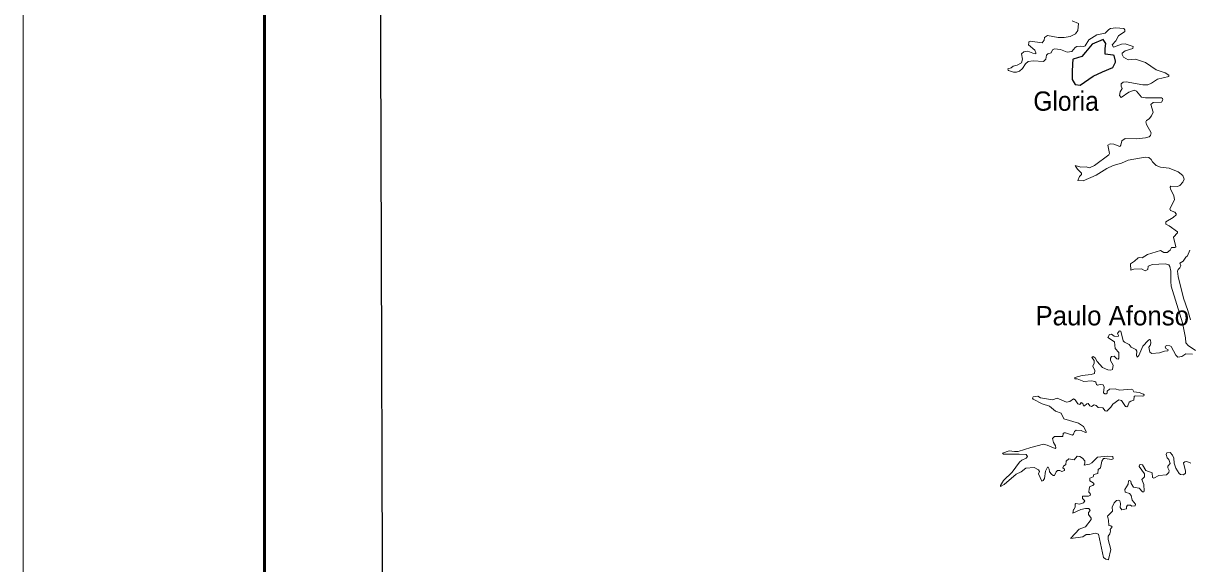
# Model space of a CAD drawing. Extents: x 553962 to 842807, y 8883888 to 9032388.
# Drawn here: x 553962 to 584142, y 8954118 to 8968117 of the extents above; entities that cross this region are included whole.
import ezdxf
from ezdxf.enums import TextEntityAlignment as Align

# ---------------------------------------------------------------- set-up
doc = ezdxf.new("R2010")
doc.units = 0
doc.header["$LTSCALE"] = 160
for name, color, linetype, lineweight in [('1', 7, 'Continuous', 13), ('21', 7, 'Continuous', 25), ('28', 7, 'Continuous', 13)]:
    doc.layers.add(name, color=color, linetype=linetype, lineweight=lineweight)
doc.layers.add('29', color=7, linetype='Continuous')

msp = doc.modelspace()

# ---------------------------------------------------------------- linework, layer by layer
at = {"layer": '1'}
msp.add_lwpolyline([(842807.3, 9032387.8), (842807.3, 8883887.8), (553961.7, 8883887.8), (553961.7, 9032387.8)], close=True, dxfattribs=at)
at = {"layer": '1', "lineweight": 53}
msp.add_lwpolyline([(840307.3, 9029887.8), (840307.3, 8886387.8), (560211.7, 8886387.8), (560211.7, 9029887.8)], close=True, dxfattribs=at)
at = {"layer": '1', "lineweight": 25}
msp.add_lwpolyline([(563033.9, 9026438.8), (793061.1, 9026438.8), (793495.6, 8889836.8), (563468.3, 8889836.8)], close=True, dxfattribs=at)
at = {"layer": '21', "lineweight": 13}
for points in [[(581126.5, 8968182.3), (581290, 8968109.6), (581273.1, 8967931.4), (581209.4, 8967844.3), (581071.3, 8967774.2), (580918.4, 8967748.8), (580765.4, 8967750.9), (580485.3, 8967797.5), (580404.5, 8967748.8), (580399.9, 8967680.5), (580349.3, 8967615), (580036, 8967653.3), (580002.2, 8967641.4), (579997.9, 8967607)], [(579471.8, 8966890.6), (579601.1, 8966852.3), (579686.3, 8966854.5), (579762.8, 8966875.7), (579835, 8966943.6), (579915.9, 8967069.1), (579983.5, 8967124), (580111.4, 8967147.6), (580385.3, 8967130.7), (580438.2, 8967185.8), (580457.7, 8967294.3), (580493.6, 8967323.8), (580582.4, 8967349.3), (580614.4, 8967431.8), (580667.5, 8967459.7), (580825.2, 8967438.5), (580998.9, 8967368.6), (581119.9, 8967389.7), (581198.8, 8967489.5), (581241.1, 8967517), (581332, 8967527.8), (581427.3, 8967517.2), (581459.8, 8967529.9), (581553.6, 8967684.9), (581763.8, 8967818.8), (581982.3, 8967861.3), (582071.9, 8967959), (582116.5, 8967984.5), (582256.4, 8967999.4), (582458.3, 8967980.2), (582488.1, 8967944.1), (582488.1, 8967904.1), (582326.8, 8967791.2), (582254.4, 8967663.6), (582159.1, 8967561.8), (582195.1, 8967498.2), (582401.1, 8967574.5), (582494.3, 8967589.4), (582706.9, 8967517.1), (582694, 8967461.9), (582494.8, 8967400.4), (582416.1, 8967347.1), (582416, 8967311.4), (582456.7, 8967236.5), (582571.1, 8967166.8), (582760.3, 8967185.7), (583025.6, 8967098.7), (583297.3, 8966909.8), (583531.2, 8966831), (583624.6, 8966771.3), (583624.5, 8966739.8), (583331.5, 8966667.5), (583178.8, 8966563.5), (583085.1, 8966527.3), (582953.4, 8966525.2), (582524.1, 8966597.4), (582441.5, 8966588.8), (582396.9, 8966552.7), (582390.2, 8966492.9), (582415.8, 8966429.6), (582364.9, 8966338), (582346, 8966247.1), (582396.7, 8966191.8), (582588.1, 8966331.8), (582728.2, 8966384.9), (582789.8, 8966359.4), (582915.7, 8966200), (583025.6, 8966183.2), (583439.6, 8966189.4), (583465.2, 8966170.4), (583475.9, 8966134.3), (583441.9, 8966077), (583223.5, 8966068.5), (583165.9, 8966013.2), (583225.2, 8965811.2), (583178, 8965717.2), (583114.8, 8965645.7), (583049.1, 8965601.1), (583034.2, 8965562.9), (583051.2, 8965492.5), (583170, 8965280.6), (583148.8, 8965212.4), (583119.2, 8965176.5), (583025.6, 8965146.5), (582792, 8965127.4), (582498.3, 8965133.6), (582407.6, 8965076.4), (582384.1, 8964957.7), (582356.2, 8964921.4), (582201.2, 8964983), (582107.7, 8964995.5), (582107.7, 8964995.5), (582044.3, 8964959.3), (582095.1, 8964745.1), (582073.9, 8964708.9), (581702.2, 8964430.7), (581572.4, 8964375.4), (581483.4, 8964396.6), (581351.7, 8964392.4), (581198.1, 8964430.9), (581209.9, 8964412.9)], [(579997.9, 8967607), (579992.3, 8967561.8), (580161, 8967421.7), (580187.4, 8967349.7), (580181.1, 8967330.4), (580105, 8967343), (580105, 8967343), (579979.2, 8967396.1), (579873.1, 8967378.9), (579813.9, 8967330.2), (579835, 8967188.5), (579811.7, 8967092.6), (579704, 8967033.2), (579595, 8967007.3), (579541.6, 8966967.5), (579455.3, 8966936.2), (579467.6, 8966902.2), (579471.8, 8966890.6)], [(581209.9, 8964412.9), (581258.4, 8964339.1), (581362.3, 8964235), (581362.2, 8964201), (581311.5, 8964150.2), (581271.6, 8964044.5), (581411.2, 8964039.8), (581742.6, 8964184.2), (582018.8, 8964356.3), (582184.7, 8964432.8), (582405.6, 8964492.4), (582571.3, 8964568.8), (583013.2, 8964651.5)], [(583013.2, 8964651.5), (583110.6, 8964638.7), (583174.1, 8964592.2), (583202.2, 8964526), (583302.1, 8964434.8), (583412.2, 8964392.4), (583632.9, 8964364.8), (583871.3, 8964269), (583992.3, 8964171.2), (584023.8, 8964077.5), (583992, 8964005.7), (583909.5, 8963912.6), (583854.1, 8963889), (583680, 8963897.4), (583661, 8963870), (583667.3, 8963822.9), (583756.3, 8963657.4), (583773.3, 8963547.2), (583654.7, 8963312.4), (583667.3, 8963264.5), (583784.2, 8963226), (583820, 8963181), (583815.2, 8963159.7), (583737.5, 8963086.2), (583548.2, 8962977.4), (583552.7, 8962911.8), (583639.8, 8962873.4), (583854, 8962716.3), (583853.2, 8962685.6), (583752.2, 8962580.2), (583807.2, 8962323.5), (583781.6, 8962306.4), (583692.8, 8962310.5), (583662.8, 8962238.5), (583584.3, 8962176.9), (583497.2, 8962176.9), (583410.3, 8962234), (583076.4, 8962125.7), (582940.9, 8962038.9), (582866.3, 8962051.4), (582832.4, 8962038.7), (582741.2, 8961953.9), (582632.6, 8961889.8), (582642.1, 8961718.4), (582724.2, 8961752), (582923.6, 8961760.4), (583013.1, 8961707.5), (583082.9, 8961741.4), (583093.8, 8961826.3), (583208.6, 8961873.1), (583535.2, 8961883.6), (583631.9, 8961861.4), (583656.7, 8961812.9), (583679.9, 8961694.8), (583675.7, 8961427), (583690.5, 8961308.2), (583979.3, 8960356.6), (584055.9, 8959969.5), (584064.3, 8959836.4), (584126, 8959774.3), (584315, 8959638.2)], [(584187.7, 8960432.6), (584121.2, 8960674.7), (584009.2, 8960993.4), (583869, 8961554.4), (583856.2, 8961694.6), (583866.6, 8961740.8), (583913.5, 8961781.7), (583936.8, 8961830.6), (583913.8, 8961907.2), (584002.7, 8961956), (584066.4, 8962055.5), (584113.2, 8962091.9), (584172.1, 8962236.3)], [(582299.4, 8960082.5), (582322.5, 8960029), (582315.9, 8960001.7), (582208.1, 8960016.5), (582141.7, 8960063.2), (582091.2, 8960052.6), (582050.7, 8959980.4), (582220.4, 8959865.6), (582237.6, 8959695.7), (582330.8, 8959589.7), (582331, 8959439.1), (582316.1, 8959415.5), (582278, 8959423.9), (582214.1, 8959495.9), (582142.1, 8959487.4), (582116.5, 8959440.5), (582118.7, 8959385.4), (582188.6, 8959260.2), (582167.3, 8959147.5), (582129.4, 8959128.6), (582046.5, 8959141.3), (581908.3, 8959202.9), (581774.6, 8959353.5), (581717.2, 8959451.2), (581670.4, 8959485.2), (581634.5, 8959460), (581691.6, 8959378.9), (581692.1, 8959315.5), (581659.8, 8959239), (581708.6, 8959122.1), (581699.9, 8959047.7), (581615.1, 8959015.9), (581381.2, 8958994.6), (581190.6, 8958937.3), (581194.6, 8958907.9), (581251.8, 8958907.5), (581424.2, 8958839.7), (581627.9, 8958854.5), (581712.6, 8958841.7), (581738.2, 8958822.6), (581757.5, 8958761.1), (581780.6, 8958746.3), (581848.8, 8958761), (581922.9, 8958748.3), (581955, 8958692.5), (581933.7, 8958544.9), (581967.3, 8958516.9), (582005.7, 8958514.7), (582027, 8958531.6), (582031.7, 8958591.2), (582095.5, 8958639.9), (582235.7, 8958646.3), (582353.6, 8958614.5), (582656.2, 8958635.6), (582696.2, 8958625.2), (582719.7, 8958570.1), (582859.9, 8958554.9), (582974.4, 8958510.4), (582989.4, 8958491.2), (582983.1, 8958470.1), (582953.2, 8958455.2), (582755.7, 8958467.7), (582732.5, 8958448.5), (582721.7, 8958357.6), (582641.2, 8958331.9), (582596.6, 8958300), (582568.8, 8958204.3), (582543.4, 8958185.4), (582505.1, 8958189.8), (582401, 8958344.6), (582332.9, 8958361.5), (582178.1, 8958253.3), (582127.2, 8958170.8), (582019.4, 8958072.8), (581978.5, 8958081.4), (581920, 8958154), (581799.4, 8958164.3), (581748.9, 8958212.8), (581696, 8958236.1), (581627.9, 8958191.9), (581578.9, 8958209), (581539.6, 8958263.8), (581539.6, 8958263.8), (581504.7, 8958259.6), (581447.3, 8958208.8), (581420.4, 8958210.8), (581400.5, 8958268.1), (581360.2, 8958291.4), (581319.8, 8958245), (581270.9, 8958257.8), (581203.2, 8958359.3), (581156.5, 8958384.9), (581064.7, 8958323.4), (580973.9, 8958304.4), (580740.2, 8958401.9), (580612.5, 8958359.6), (580303, 8958410.4), (580235.9, 8958453.9), (580113.2, 8958444.3), (580098.5, 8958410.3), (580099.6, 8958407.9)], [(584244.7, 8959542.8), (584070.6, 8959557.6), (583962.4, 8959487.6), (583862.6, 8959466.3), (583809.5, 8959521.5), (583684, 8959740.2), (583651.7, 8959765.9), (583580.3, 8959774.3), (583541.6, 8959757), (583531.3, 8959731.8), (583550.2, 8959691.6), (583607.5, 8959661.8), (583603.4, 8959628), (583514.4, 8959627.7), (583382, 8959578.8), (583184.5, 8959559.9), (583138.3, 8959595.9), (583108.6, 8959723.3), (583108.6, 8959723.3), (583144.6, 8959774.5), (583159.4, 8959833.8), (583148.8, 8959914.2), (583125.3, 8959922.9), (583089.5, 8959901.9), (582957.8, 8959753.2), (582851.4, 8959515.1), (582809, 8959470.7), (582792, 8959510.9), (582795.6, 8959619.4), (582771.8, 8959670.2), (582656.1, 8959725.5), (582596.3, 8959797.7), (582477.6, 8959853), (582443.6, 8959893.3), (582381.9, 8960139.6), (582362.8, 8960152.2), (582339.6, 8960143.8), (582299.4, 8960082.5)], [(580099.6, 8958407.9), (580111.4, 8958382.8), (580349.1, 8958255.5), (580540.2, 8958198), (580692.5, 8958073.2), (580835.5, 8958013.2), (580910.1, 8957870.9), (581289.9, 8957760.6), (581421.8, 8957673.3), (581496, 8957526.9), (581466.2, 8957520.6), (581357.9, 8957571.4), (581224.5, 8957577.8), (581188.5, 8957544.2), (581162.8, 8957476.1), (581130.8, 8957450.5), (580955.2, 8957509.6), (580919.1, 8957507.7), (580890.9, 8957486.6), (580886.3, 8957410), (580667.8, 8957416.2), (580619.2, 8957363.6), (580640, 8957259.4), (580693.2, 8957169.7), (580701.6, 8957122.8), (580682.8, 8957104.2), (580477.4, 8957190.9), (580383.3, 8957210.3), (580056.8, 8957131.9), (579729, 8957025.6), (579635.1, 8957021.3), (579494.9, 8957040.3), (579320.1, 8956982.2), (579330.4, 8956970.9)], [(579330.4, 8956970.9), (579346.5, 8956953.4), (579750.3, 8956955.4), (579931, 8956942.9), (579964.5, 8956895.9), (579936.8, 8956853.3), (579818, 8956796.1), (579763, 8956751.6), (579569.6, 8956488.2), (579346.5, 8956275.5), (579267.5, 8956147.6), (579269.2, 8956128.5)], [(582066.7, 8954223.6), (582129.2, 8954489.4), (582057, 8954744.1), (582052.8, 8954828.8), (582103.7, 8954893.1), (582120.6, 8954960.7), (582108.2, 8955005.5), (582163, 8955071.2), (582129.2, 8955100.8), (582072.2, 8955107.3), (582061.2, 8955249.4), (582040.1, 8955351.6), (582171.5, 8955478.9), (582157.1, 8955581.8), (582214, 8955691.2), (582269.6, 8955750.9), (582321.7, 8955763.6), (582358.6, 8955744.6), (582379.8, 8955678.5), (582367.2, 8955576.8), (582411.8, 8955511), (582534.7, 8955540.7), (582532.9, 8955594), (582558.3, 8955632), (582632.4, 8955638.4), (582671.6, 8955604.4), (582751.6, 8955613.2), (582766.3, 8955661.9), (582675.3, 8955763.5), (582649.7, 8955884.6), (582613.2, 8955937.9), (582498.8, 8955974.4), (582492.5, 8956044.1), (582570.9, 8956175.6), (582579.8, 8956265), (582607.4, 8956273.4), (582645.2, 8956252.4), (582652.2, 8956196.2), (582711.3, 8956099.4), (582856.3, 8956071.3), (582947.1, 8955976.2), (582976.7, 8955976.2), (582991.4, 8955993), (582978.9, 8956171.6), (582932.2, 8956297.6), (582995.8, 8956371.3), (583000.1, 8956445.4), (583000.1, 8956445.4), (582857.8, 8956639.1), (582866.4, 8956681.3), (582889.9, 8956689.8), (582944.7, 8956675), (583036.3, 8956532.7), (583197.6, 8956473.1), (583204.2, 8956354.3), (583235.8, 8956333.2), (583365.5, 8956403), (583569.2, 8956422.2), (583628.9, 8956482), (583635.2, 8956528.2), (583599.3, 8956600.4), (583603.4, 8956642.9), (583660.7, 8956715.7), (583628.7, 8956817.4), (583586.5, 8956859.9), (583561.1, 8956946.9), (583580.2, 8956987.2), (583660.8, 8957002.1), (583724.4, 8956925.6), (583756.3, 8956851.3), (583767, 8956723.9), (583805.3, 8956596.4), (583896.6, 8956454.1), (583928.7, 8956432.8), (584011.2, 8956420.2), (584055.8, 8956462.4), (584062.2, 8956515.4), (584011.4, 8956727.3), (584038.7, 8956757.6), (584094.1, 8956768.4), (584197.5, 8956726)], [(579269.2, 8956128.5), (579269.9, 8956121.1), (579359.2, 8956171.6), (579677.6, 8956436.9), (579805, 8956498.6), (579924, 8956592), (580136.6, 8956613.3), (580253.4, 8956549.5), (580274.6, 8956509.1), (580251.5, 8956443.2), (580340.8, 8956252.5), (580372.3, 8956271.5), (580408.5, 8956324.5), (580431.9, 8956511.2), (580482.8, 8956619.5), (580499.8, 8956617.5), (580531.6, 8956562.6), (580540.2, 8956494.7), (580586.8, 8956433.1), (580631.7, 8956403.2), (580663.4, 8956403.2), (580708.6, 8956501.7), (580744, 8956530.4), (580801.5, 8956530.5), (580856.8, 8956505.1), (580922.4, 8956530.5), (580922.5, 8956566.6), (580882.6, 8956601.5), (580901.5, 8956645.2), (580958.6, 8956687.6), (580969.4, 8956772.7), (581041.6, 8956834.2), (581175.2, 8956811), (581251.9, 8956904.3), (581326.2, 8956893.7), (581388, 8956855.3), (581453.6, 8956783.3), (581455.8, 8956719.8), (581434.7, 8956673.2), (581572.6, 8956696.3), (581630, 8956728.1), (581783.2, 8956880.5), (581783.2, 8956880.5), (582043.8, 8956902.2), (582180, 8956896), (582182.3, 8956832.5), (582150.4, 8956819.5), (581969.4, 8956847.3), (581933.5, 8956840.4), (581891.2, 8956774.6), (581857.1, 8956604.5), (581795.2, 8956554.8), (581787.1, 8956452), (581685.3, 8956432.7), (581666, 8956369.2), (581578.8, 8956332.5), (581581.2, 8956260.8), (581665.8, 8956214.1), (581693.6, 8956177.9), (581661.8, 8956146.1), (581585.5, 8956114.1), (581562.1, 8956061.3), (581560, 8955969.8), (581593.8, 8955933.6), (581597.9, 8955895.3), (581551.4, 8955867.9), (581390.2, 8955865.7), (581390.1, 8955804.1), (581449.3, 8955742.7), (581421.9, 8955695.9), (581310.1, 8955657.7), (581215.8, 8955674.4), (581201, 8955657.4), (581200.8, 8955593.5), (581179.9, 8955534.8), (581160.6, 8955521.3), (581145.7, 8955426.2), (581352.5, 8955521.7), (581466.4, 8955547), (581559.6, 8955544.9), (581591.7, 8955496), (581547.2, 8955446.9), (581547.2, 8955390.1), (581619.2, 8955294.3), (581619.3, 8955264.8), (581466.6, 8955071.4), (581309.3, 8955015.9), (581086.2, 8954783.2), (581087.4, 8954777.9)], [(581087.4, 8954777.9), (581089.5, 8954768.8), (581402.7, 8954812.1), (581483.7, 8954877.8), (581585.7, 8954873.7), (581719.8, 8954905.5), (581803.6, 8954880.3), (581939.2, 8954279.2), (581995.8, 8954238.9), (582065.2, 8954217.4), (582066.7, 8954223.6)]]:
    msp.add_lwpolyline(points, dxfattribs=at)
at = {"layer": '28', "lineweight": 25}
msp.add_lwpolyline([(581144.7, 8967182.6), (581135.4, 8967071.1), (581126.2, 8966848.2), (581126.2, 8966662.4), (581200.4, 8966532.3), (581330.4, 8966513.8), (581664.7, 8966746), (581906.1, 8966857.5), (582175.4, 8966968.9), (582249.7, 8967108.2), (582249.7, 8967136.1), (582212.6, 8967284.7), (582184.7, 8967294), (581980.4, 8967321.9), (581980.4, 8967461.2), (581999, 8967591.2), (581924.7, 8967693.4), (581646.1, 8967572.7), (581469.7, 8967368.3), (581376.9, 8967256.9), (581154, 8967191.8)], close=True, dxfattribs=at)

# ---------------------------------------------------------------- texts
at = {"layer": '29', "width": 0.95}
msp.add_text('Gloria', height=500, dxfattribs=at).set_placement((580966.6, 8965851.8), align=Align.CENTER)
at = {"layer": '29'}
msp.add_text('Paulo Afonso', height=500, dxfattribs=at).set_placement((582161.5, 8960292.1), align=Align.CENTER)

doc.saveas('drawing.dxf')
